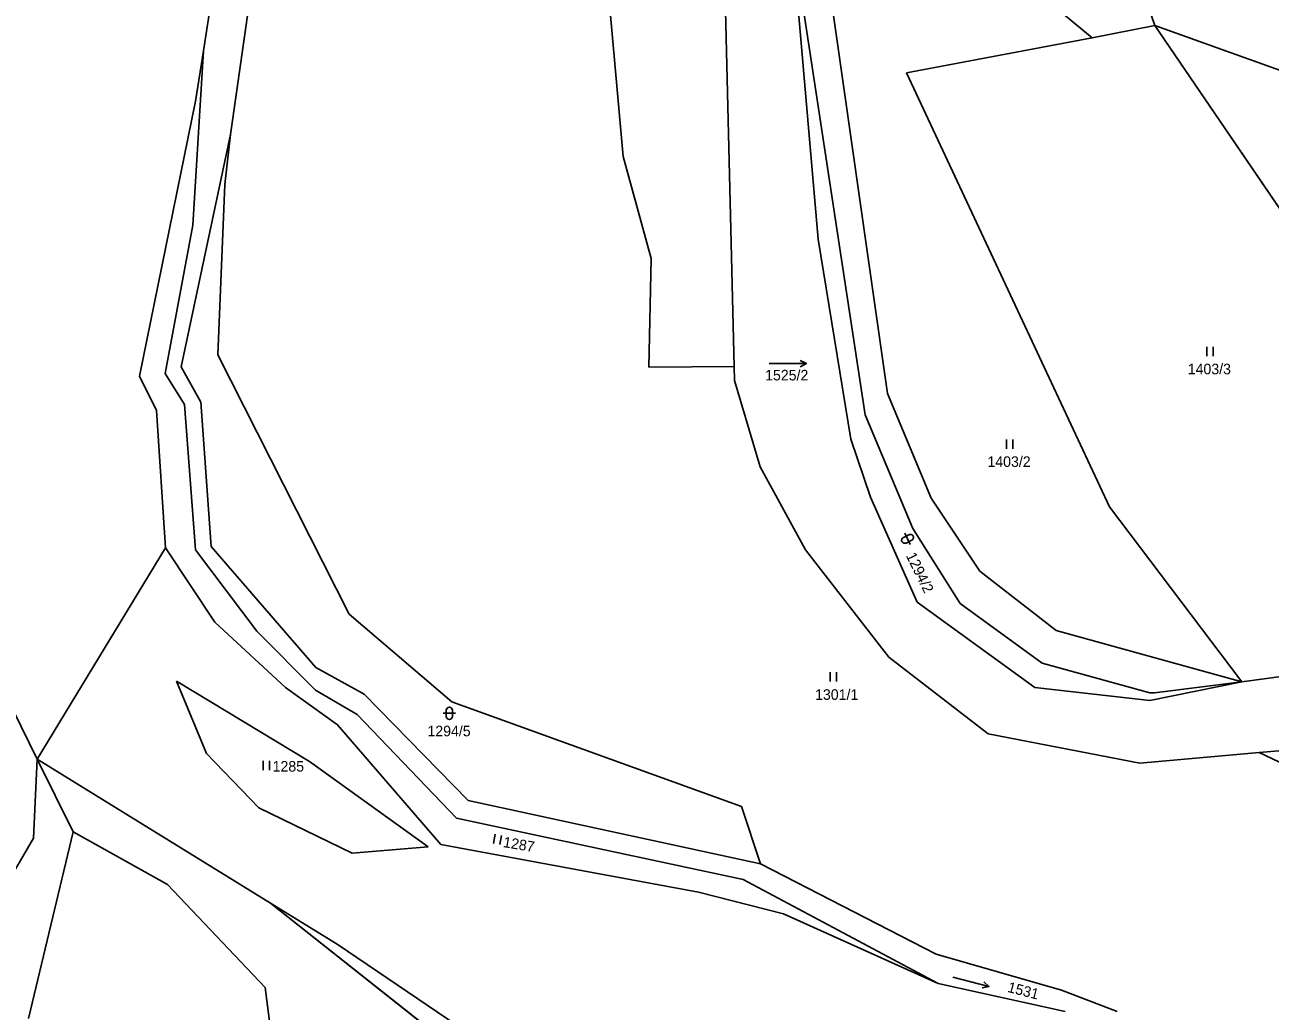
# Model space of a CAD drawing. Extents: x -760642 to -757221, y -1092371 to -1088855.
# Drawn here: x -759072.9 to -758872.5, y -1091408.1 to -1091249.4 of the extents above; entities that cross this region are included whole.
import ezdxf

# ---------------------------------------------------------------- set-up
doc = ezdxf.new("R2010")
doc.units = 0
for name, color, linetype in [('Vrstva 1', 7, 'Continuous'), ('Vrstva 18', 7, 'Continuous'), ('Vrstva 25', 7, 'Continuous'), ('Vrstva 30', 7, 'Continuous')]:
    doc.layers.add(name, color=color, linetype=linetype)

msp = doc.modelspace()

# ---------------------------------------------------------------- linework, layer by layer
at = {"layer": 'Vrstva 1'}
for p, q in [((-758982.43, -1091205.94), (-758976.57, -1091270.58)), ((-758901.11, -1091251.46), (-758944.43, -1091215.55)), ((-759038.65, -1091218.73), (-759044.14, -1091253.55)), ((-758960.76, -1091219.38), (-758958.7, -1091304.39)), ((-759033.13, -1091220.56), (-759039.79, -1091267.02)), ((-758949.54, -1091234.06), (-758937.62, -1091312.14)), ((-758945.21, -1091283.87), (-758949.54, -1091234.06)), ((-758943.48, -1091242.67), (-758934.05, -1091308.74)), ((-758893.54, -1091242.33), (-758891, -1091249.5)), ((-758891, -1091249.5), (-758901.11, -1091251.46)), ((-758891, -1091249.5), (-758867.96, -1091257.78)), ((-758845.54, -1091316.24), (-758891, -1091249.5)), ((-758930.99, -1091257.1), (-758901.11, -1091251.46)), ((-759045.81, -1091281.63), (-759044.14, -1091253.55)), ((-759044.14, -1091253.55), (-759045.42, -1091261.68)), ((-758930.99, -1091257.1), (-758898.32, -1091326.97)), ((-759045.42, -1091261.68), (-759054.43, -1091305.91)), ((-759047.7, -1091304.44), (-759039.79, -1091267.02)), ((-759039.79, -1091267.02), (-759040.7, -1091275.1)), ((-758976.57, -1091270.58), (-758972.05, -1091287.01)), ((-759040.7, -1091275.1), (-759041.83, -1091302.52)), ((-759045.81, -1091281.63), (-759050.31, -1091305.48)), ((-758939.92, -1091316.07), (-758945.21, -1091283.87)), ((-758972.05, -1091287.01), (-758972.45, -1091304.49)), ((-759044.56, -1091310.1), (-759047.7, -1091304.44)), ((-759041.83, -1091302.52), (-759020.69, -1091344.24)), ((-758972.45, -1091304.49), (-758958.7, -1091304.39)), ((-758958.7, -1091304.39), (-758958.65, -1091306.61)), ((-759054.43, -1091305.91), (-759051.7, -1091311.44)), ((-759050.31, -1091305.48), (-759047.17, -1091310.51)), ((-758958.65, -1091306.61), (-758954.55, -1091320.52)), ((-759042.89, -1091333.34), (-759044.56, -1091310.1)), ((-758934.05, -1091308.74), (-758926.99, -1091325.56)), ((-759051.7, -1091311.44), (-759050.23, -1091333.55)), ((-759047.17, -1091310.51), (-759045.38, -1091333.86)), ((-758937.62, -1091312.14), (-758929.95, -1091330.45)), ((-758936.75, -1091325.41), (-758939.92, -1091316.07)), ((-758954.55, -1091320.52), (-758947.25, -1091333.88)), ((-759091.43, -1091325.84), (-759070.89, -1091367.57)), ((-758929.28, -1091342.31), (-758936.75, -1091325.41)), ((-758926.99, -1091325.56), (-758919.17, -1091337.3)), ((-758898.32, -1091326.97), (-758877.02, -1091355.14)), ((-758929.95, -1091330.45), (-758922.34, -1091342.52)), ((-759050.23, -1091333.55), (-759070.89, -1091367.57)), ((-759050.23, -1091333.55), (-759042.28, -1091345.55)), ((-759045.38, -1091333.86), (-759035.54, -1091346.97)), ((-759026.03, -1091352.81), (-759042.89, -1091333.34)), ((-758947.25, -1091333.88), (-758933.84, -1091351.15)), ((-758919.17, -1091337.3), (-758906.88, -1091346.86)), ((-758910.33, -1091356.07), (-758929.28, -1091342.31)), ((-758922.34, -1091342.52), (-758909.13, -1091352.15)), ((-759020.69, -1091344.24), (-759004.15, -1091358.35)), ((-759042.28, -1091345.55), (-759030.94, -1091356.04)), ((-759035.54, -1091346.97), (-759026.11, -1091356.5)), ((-758906.88, -1091346.86), (-758877.02, -1091355.14)), ((-758933.84, -1091351.15), (-758917.86, -1091363.49)), ((-758909.13, -1091352.15), (-758891.84, -1091356.88)), ((-759018.27, -1091357.11), (-759026.03, -1091352.81)), ((-758877.02, -1091355.14), (-758860.43, -1091352.87)), ((-759048.47, -1091355), (-759027.04, -1091367.98)), ((-759043.66, -1091366.67), (-759048.47, -1091355)), ((-759030.94, -1091356.04), (-759022.56, -1091362.05)), ((-759026.11, -1091356.5), (-759019.4, -1091360.38)), ((-758910.33, -1091356.07), (-758891.81, -1091358.13)), ((-758891.81, -1091358.13), (-758877.02, -1091355.14)), ((-758891.09, -1091356.91), (-758877.02, -1091355.14)), ((-759001.52, -1091374.25), (-759018.27, -1091357.11)), ((-759004.15, -1091358.35), (-758957.53, -1091375.22)), ((-758891.84, -1091356.88), (-758891.09, -1091356.91)), ((-759019.4, -1091360.38), (-759003.39, -1091377.08)), ((-759022.56, -1091362.05), (-759005.91, -1091381.31)), ((-758917.86, -1091363.49), (-758893.45, -1091368.2)), ((-758893.45, -1091368.2), (-758874.2, -1091366.5)), ((-758874.2, -1091366.5), (-758865.72, -1091365.76)), ((-758806.11, -1091399.16), (-758874.2, -1091366.5)), ((-759070.89, -1091367.57), (-759071.48, -1091380.29)), ((-759070.89, -1091367.57), (-759065.08, -1091379.29)), ((-759033.32, -1091390.76), (-759070.89, -1091367.57)), ((-759035.2, -1091375.42), (-759043.66, -1091366.67)), ((-759027.04, -1091367.98), (-759007.94, -1091381.7)), ((-758954.45, -1091384.4), (-759001.52, -1091374.25)), ((-759020.18, -1091382.72), (-759035.2, -1091375.42)), ((-758957.53, -1091375.22), (-758954.45, -1091384.4)), ((-759003.39, -1091377.08), (-758957.29, -1091386.93)), ((-759071.48, -1091380.29), (-759094.05, -1091419.03)), ((-759065.08, -1091379.29), (-759072.26, -1091409.34)), ((-759065.08, -1091379.29), (-759049.93, -1091387.73)), ((-759007.94, -1091381.7), (-759020.18, -1091382.72)), ((-759005.91, -1091381.31), (-758964.45, -1091388.97)), ((-758954.45, -1091384.4), (-758926.23, -1091398.99)), ((-759049.93, -1091387.73), (-759034.19, -1091404.31)), ((-758957.29, -1091386.93), (-758925.9, -1091403.68)), ((-758964.45, -1091388.97), (-758950.79, -1091392.47)), ((-758994.53, -1091421.46), (-759033.32, -1091390.76)), ((-759022.6, -1091397.37), (-759033.32, -1091390.76)), ((-758950.79, -1091392.47), (-758925.9, -1091403.68)), ((-758983.6, -1091423.73), (-759022.6, -1091397.37)), ((-758926.23, -1091398.99), (-758906.01, -1091404.76)), ((-759034.19, -1091404.31), (-759032.3, -1091419.1)), ((-758925.9, -1091403.68), (-758905.47, -1091408.19)), ((-758906.01, -1091404.76), (-758897.1, -1091408.22))]:
    msp.add_line(p, q, dxfattribs=at)
at = {"layer": 'Vrstva 25'}
for p, q in [((-758882.627, -1091301.195), (-758882.627, -1091302.695)), ((-758881.605, -1091302.695), (-758881.605, -1091301.195)), ((-758953.09, -1091303.92), (-758947.09, -1091303.92)), ((-758914.877, -1091316.105), (-758914.877, -1091317.605)), ((-758913.855, -1091317.605), (-758913.855, -1091316.105)), ((-758931.481, -1091331.891), (-758930.584, -1091331.45)), ((-758931.253, -1091331.222), (-758930.372, -1091333.017)), ((-758931.041, -1091332.789), (-758930.143, -1091332.348)), ((-758943.287, -1091353.595), (-758943.287, -1091355.095)), ((-758942.265, -1091355.095), (-758942.265, -1091353.595)), ((-759005.54, -1091360.2), (-759003.54, -1091360.2)), ((-759005.04, -1091360.7), (-759005.04, -1091359.7)), ((-759004.04, -1091360.7), (-759004.04, -1091359.7)), ((-759034.507, -1091367.845), (-759034.507, -1091369.345)), ((-759033.485, -1091369.345), (-759033.485, -1091367.845)), ((-758997.183, -1091379.673), (-758997.431, -1091381.153)), ((-758996.423, -1091381.322), (-758996.175, -1091379.842)), ((-758923.526, -1091402.664), (-758917.714, -1091404.156))]:
    msp.add_line(p, q, dxfattribs=at)
for points in [[(-758948.09, -1091303.42), (-758947.09, -1091303.92), (-758948.09, -1091304.42)], [(-758918.558, -1091403.423), (-758917.714, -1091404.156), (-758918.807, -1091404.391)]]:
    msp.add_lwpolyline(points, dxfattribs=at)
for centre, start, end in [((-758931.261, -1091332.34), 116.14095, 296.14095), ((-758930.363, -1091331.899), 296.14095, 116.14095), ((-759004.54, -1091359.7), 0, 180), ((-759004.54, -1091360.7), 180, 0)]:
    msp.add_arc(centre, 0.5, start, end, dxfattribs=at)
at = {"layer": 'Vrstva 30'}
for points in [[(-758766.65, -1091353.45), (-758758.59, -1091318.16), (-758734.25, -1091259.03), (-758747.36, -1091244.58), (-758803.14, -1091243.75), (-758802.03, -1091259.49), (-758807.34, -1091278.33), (-758817.79, -1091281.25), (-758829.94, -1091283.47), (-758844.67, -1091278.16), (-758867.96, -1091257.78), (-758891, -1091249.5), (-758845.54, -1091316.24), (-758819.03, -1091339.76), (-758808.86, -1091345.43), (-758822.37, -1091350.43), (-758789.76, -1091358.53), (-758766.65, -1091353.45)], [(-759004.76, -1091441.33), (-758994.53, -1091421.46), (-759033.32, -1091390.76), (-759070.89, -1091367.57), (-759065.08, -1091379.29), (-759049.93, -1091387.73), (-759034.19, -1091404.31), (-759032.3, -1091419.1), (-759021.37, -1091438), (-759004.76, -1091441.33)]]:
    msp.add_lwpolyline(points, dxfattribs=at)

# ---------------------------------------------------------------- texts
at = {"layer": 'Vrstva 18'}
for s, p in [('1403/3', (-758885.718, -1091305.63)), ('1525/2', (-758953.733, -1091306.62)), ('1403/2', (-758917.956, -1091320.54)), ('1301/1', (-758945.69, -1091358.03)), ('1294/5', (-759008.076, -1091363.9)), ('1285', (-759032.99, -1091369.58))]:
    msp.add_text(s, height=1.7, dxfattribs=at).set_placement(p)
for s, rotation, p in [('1294/2', 296.14086, (-758931.11, -1091334.8)), ('1287', 350.47773, (-758995.979, -1091381.716)), ('1531', 345.60639, (-758914.828, -1091405.024))]:
    msp.add_text(s, height=1.7, rotation=rotation, dxfattribs=at).set_placement(p)

doc.saveas('drawing.dxf')
